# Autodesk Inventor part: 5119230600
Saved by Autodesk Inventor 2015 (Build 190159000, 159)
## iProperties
Created: 2020-07
Part Number: 5119230600
Checked By: TraceParts S.A.
Material: Generic
Catalog Web Link: www.traceparts.com
Document SubType Name: Modeling
Designer: TraceParts
Density: 1 g/cm^3
Appearance: Default
Company: TraceParts S.A.
Author: TraceParts
REFERENCE: 5119230600
DESIGN: HIT-1000 P 0,37KW (230/400V 50HZ) - 5119230600
SUPPLIER: Soler & Palau
TraceParts.PartNumber: 10-20122018-119595
TraceParts.PartTitle: HIB-P/HIT-P
TraceParts.InstanceId: 10-20122018-119595850VORIF6F0565QZRFBZNOZDC
TraceParts.PartStatus: Published
TraceParts.PartVersion: 1.0.2
TRACEPARTS: TRACEPARTS
TraceParts.PartLanguage: en
TraceParts.ClassPath: SOLER_PALAU:10-20122018-119595
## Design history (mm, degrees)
feature "5119230600"
body "Solid1"
